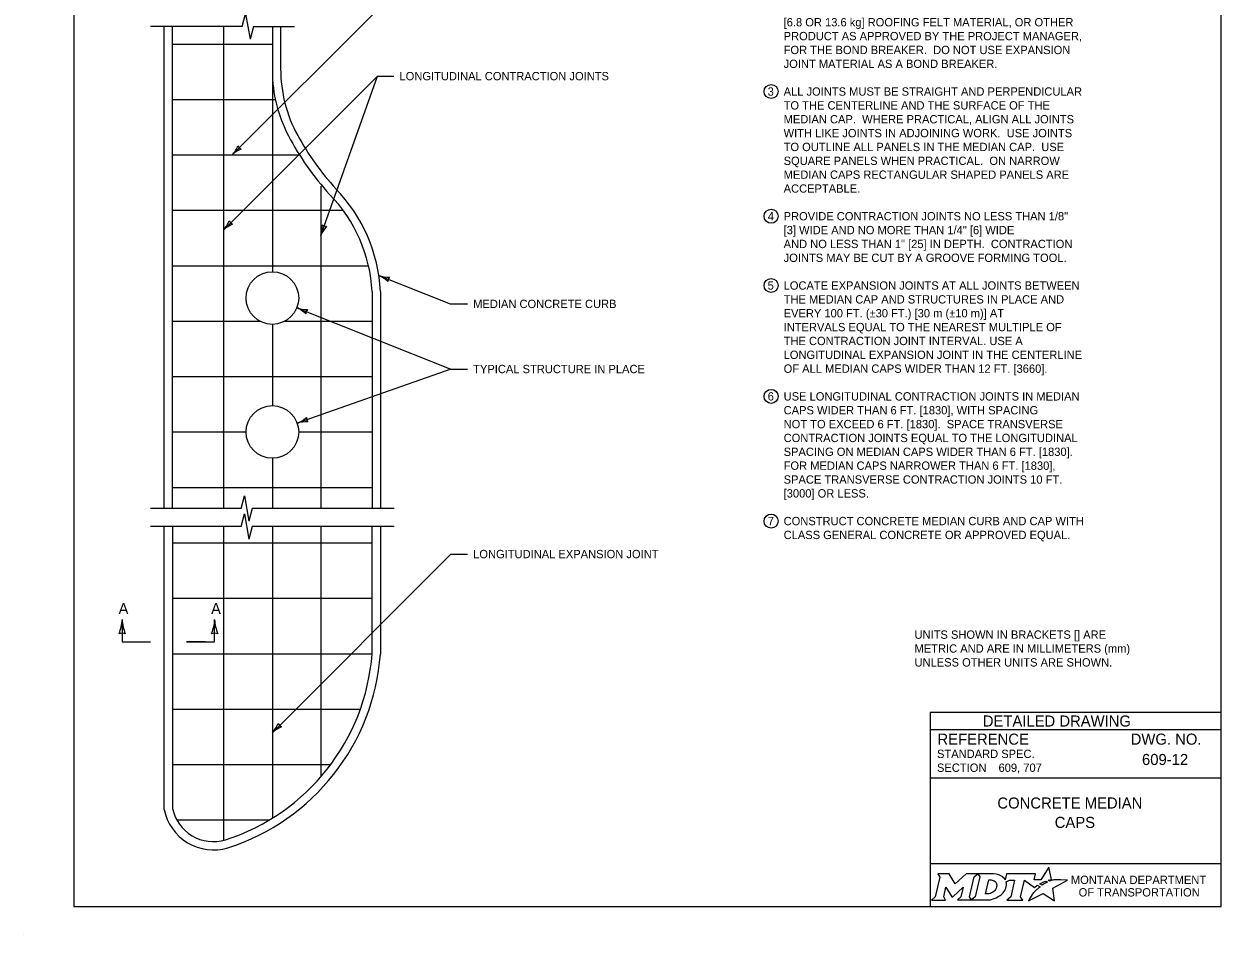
# Model space of a CAD drawing. Extents: x 49991.4 to 50021, y 49987.6 to 50011.4.
# Drawn here: x 49999.98 to 50008.61, y 49999.86 to 50006.43 of the extents above; entities that cross this region are included whole.
import ezdxf

# ---------------------------------------------------------------- set-up
doc = ezdxf.new("R2010")
doc.units = 0
for name, color, linetype in [('Level 1', 7, 'Continuous'), ('Level 2', 7, 'Continuous'), ('Level 3', 7, 'Continuous'), ('Level 6', 7, 'Continuous')]:
    doc.layers.add(name, color=color, linetype=linetype)

msp = doc.modelspace()

# ---------------------------------------------------------------- linework, layer by layer
at = {"layer": 'Level 1'}
for p, q in [((50000.989, 50002.9346), (50000.989, 50006.4113)), ((50001.049, 50002.9346), (50001.049, 50006.4113)), ((50001.4159, 50006.4113), (50001.4159, 50002.9346)), ((50001.769, 50006.4113), (50001.769, 50006.0906)), ((50001.829, 50006.4113), (50001.829, 50006.1057)), ((50001.049, 50006.2857), (50001.769, 50006.2857)), ((50001.769, 50006.0906), (50001.769, 50004.6426)), ((50001.049, 50005.8857), (50001.7902, 50005.8857)), ((50001.049, 50005.4857), (50001.9646, 50005.4857)), ((50002.119, 50005.2604), (50002.119, 50002.9346)), ((50001.049, 50005.0857), (50002.2794, 50005.0857)), ((50001.049, 50004.6857), (50002.4628, 50004.6857)), ((50002.489, 50004.4989), (50002.489, 50002.9346)), ((50002.549, 50004.5005), (50002.549, 50002.9346)), ((50001.049, 50004.2857), (50001.6782, 50004.2857)), ((50001.769, 50004.2626), (50001.769, 50003.6757)), ((50001.8598, 50004.2857), (50002.489, 50004.2857)), ((50001.049, 50003.8857), (50002.489, 50003.8857)), ((50001.049, 50003.4857), (50001.579, 50003.4857)), ((50001.959, 50003.4857), (50002.489, 50003.4857)), ((50001.769, 50003.2957), (50001.769, 50002.9346)), ((50001.049, 50003.0857), (50002.489, 50003.0857)), ((50000.989, 50000.7623), (50000.989, 50002.8048)), ((50001.049, 50002.8048), (50001.049, 50000.7683)), ((50001.4159, 50002.8048), (50001.4159, 50000.5374)), ((50001.769, 50002.8048), (50001.769, 50000.6987)), ((50002.119, 50002.8048), (50002.119, 50000.9971)), ((50002.489, 50001.8857), (50002.489, 50002.8048)), ((50002.549, 50002.8048), (50002.549, 50001.8834)), ((50001.049, 50002.6857), (50002.489, 50002.6857)), ((50001.049, 50002.2857), (50002.489, 50002.2857)), ((50001.049, 50001.8857), (50002.489, 50001.8857)), ((50001.049, 50001.4857), (50002.4042, 50001.4857)), ((50001.049, 50001.0857), (50002.1902, 50001.0857)), ((50001.0798, 50000.6857), (50001.7477, 50000.6857)), ((49999.9766, 49999.8624), (49999.9766, 49999.8624))]:
    msp.add_line(p, q, dxfattribs=at)
msp.add_lwpolyline([(50008.6146, 50011.2628), (50000.3356, 50011.2628), (50000.3356, 50000.0624), (50008.6146, 50000.0624)], close=True, dxfattribs=at)
for centre in [(50001.769, 50004.4526), (50001.769, 50003.4857)]:
    msp.add_circle(centre, 0.19, dxfattribs=at)
for centre, radius, start, end in [((50002.769, 50006.0906), 1, 180, 207.84978), ((50002.829, 50006.1057), 1, 180, 208.70363), ((50003.6924, 50006.5785), 2.0444, 207.84978, 222.39165), ((50003.6924, 50006.5785), 1.9844, 208.70363, 222.39165), ((50001.4021, 50004.4415), 1.1484, 2.9454, 44.18946), ((50001.4021, 50004.4415), 1.0884, 3.02551, 44.18946), ((50001.855, 50004.1793), 0.2223, 45.76443, 65.94794), ((50002.0209, 50004.6028), 0.233, 251.13573, 270.38558), ((50002.0647, 50004.3349), 0.0548, 140.44724, 176.1696), ((50001.8601, 50003.7645), 0.233, 292.23449, 311.48434), ((50002.0692, 50003.5914), 0.0548, 181.546, 217.26836), ((50002.0134, 50003.3362), 0.2223, 86.86319, 107.0467), ((50000.961, 50002.0007), 1.5323, 287.82443, 355.6959), ((50000.961, 50002.0007), 1.5923, 287.80103, 355.77781), ((50001.3442, 50000.8312), 0.3618, 190.97588, 286.64684), ((50001.3442, 50000.8312), 0.3018, 192.02127, 286.53619)]:
    msp.add_arc(centre, radius, start, end, dxfattribs=at)
at = {"layer": 'Level 2'}
for p, q in [((50008.6146, 50001.4624), (50006.5146, 50001.4624)), ((50006.5146, 50001.4624), (50006.5146, 50000.0624)), ((50008.6146, 50001.3374), (50006.5146, 50001.3374)), ((50008.2507, 50001.1223), (50008.2507, 50001.1223)), ((50008.6146, 50000.9874), (50006.5146, 50000.9874)), ((50007.0089, 50001.0629), (50007.0089, 50001.0629)), ((50007.5646, 50000.7383), (50007.5646, 50000.7383)), ((50008.6146, 50000.3693), (50006.5146, 50000.3693))]:
    msp.add_line(p, q, dxfattribs=at)
for points in [[(50006.5701, 50000.2974), (50006.5842, 50000.274), (50006.5507, 50000.1307), (50006.525, 50000.1082), (50006.6266, 50000.1082), (50006.6131, 50000.131), (50006.6293, 50000.2011), (50006.673, 50000.1321), (50006.6783, 50000.1321), (50006.7534, 50000.2016), (50006.737, 50000.1305), (50006.7123, 50000.1085), (50006.8139, 50000.1085), (50006.8001, 50000.1318), (50006.8333, 50000.2742)], [(50006.8333, 50000.2742), (50006.8586, 50000.2974), (50006.7762, 50000.2974), (50006.6966, 50000.2244), (50006.6521, 50000.2971), (50006.5701, 50000.2974)], [(50006.9722, 50000.2974), (50006.8586, 50000.2974), (50006.8733, 50000.2745), (50006.8394, 50000.1307), (50006.8139, 50000.1085), (50006.9245, 50000.1085)], [(50007.3771, 50000.2447), (50007.3668, 50000.2503), (50007.3784, 50000.2531), (50007.39, 50000.2551), (50007.3726, 50000.3452), (50007.3131, 50000.2539), (50007.2658, 50000.2532), (50007.2761, 50000.2973), (50007.0669, 50000.2974), (50007.0568, 50000.2549), (50007.051, 50000.2632)], [(50006.9962, 50000.2107), (50006.995, 50000.2026), (50006.9918, 50000.1933), (50006.9876, 50000.1851), (50006.982, 50000.1776), (50006.9755, 50000.1707), (50006.9676, 50000.1644), (50006.9593, 50000.1597), (50006.9502, 50000.1558), (50006.9411, 50000.1535), (50006.9319, 50000.1526), (50006.916, 50000.1526), (50006.9396, 50000.2526), (50006.9556, 50000.2526), (50006.9632, 50000.252), (50006.9708, 50000.2501), (50006.9774, 50000.2471), (50006.9835, 50000.2429), (50006.9883, 50000.2379), (50006.992, 50000.2319), (50006.9947, 50000.2257), (50006.9963, 50000.2183), (50006.9963, 50000.2153), (50006.9962, 50000.2107)], [(50007.0636, 50000.2383), (50007.0882, 50000.2514), (50007.1251, 50000.2514), (50007.0965, 50000.1309), (50007.069, 50000.1082), (50007.1852, 50000.1082), (50007.1682, 50000.1311), (50007.1964, 50000.2513), (50007.2677, 50000.1996), (50007.2888, 50000.2147), (50007.3085, 50000.2038)], [(50007.2527, 50000.1479), (50007.2374, 50000.1235), (50007.2327, 50000.116), (50007.2269, 50000.1074), (50007.2246, 50000.1031), (50007.3299, 50000.1562), (50007.4138, 50000.1011), (50007.4007, 50000.1938), (50007.5076, 50000.2522), (50007.4583, 50000.253), (50007.4282, 50000.2534), (50007.4074, 50000.2537), (50007.4006, 50000.2522), (50007.3957, 50000.251), (50007.3873, 50000.2487), (50007.3771, 50000.2447)], [(50007.3267, 50000.2171), (50007.3243, 50000.2154), (50007.306, 50000.225), (50007.3163, 50000.2307), (50007.3204, 50000.2329), (50007.329, 50000.2369), (50007.3347, 50000.2395), (50007.3426, 50000.2425), (50007.3499, 50000.2452), (50007.3617, 50000.2378), (50007.3577, 50000.2357), (50007.3531, 50000.2332), (50007.3489, 50000.231), (50007.3439, 50000.2281), (50007.342, 50000.227), (50007.3393, 50000.2254), (50007.3368, 50000.224), (50007.3345, 50000.2224), (50007.3319, 50000.2206), (50007.3292, 50000.2188), (50007.3267, 50000.2171)], [(50006.9702, 50000.1158), (50006.9786, 50000.1184), (50006.9916, 50000.1238), (50007.012, 50000.1348)], [(50007.2666, 50000.164), (50007.2666, 50000.164)]]:
    msp.add_lwpolyline(points, dxfattribs=at)
for centre in [(50005.3678, 50005.9428), (50005.3678, 50005.0428), (50005.3678, 50004.5428), (50005.3678, 50003.7428), (50005.3678, 50002.8428)]:
    msp.add_circle(centre, 0.0505, dxfattribs=at)
for centre, radius, start, end in [((50006.9953, 50000.219), 0.0709, 339.53292, 15.85821), ((50006.9513, 50000.2363), 0.1183, 300.91025, 339.13831)]:
    msp.add_arc(centre, radius, start, end, dxfattribs=at)
for centre, major_axis, ratio, start_param, end_param in [((50006.9701, 50000.25), (0.0834, -0.0037), 0.568097, 0.61298, 1.570796), ((50007.0257, 50000.2573), (0.0361, -0.0295), 0.469099, 1.225588, 1.570796), ((50007.2974, 50000.1941), (-0.0112, -0.0097), 0.021651, 3.157348, 6.283185), ((50006.9248, 50000.2568), (0, 0.1484), 0.987302, 3.139398, 3.456847), ((50007.2597, 50000.1559), (-0.00694, -0.00806), 0.008222, 0, 3.137361), ((50007.2764, 50000.1742), (-0.0098, -0.0102), 0.016458, 3.141593, 6.279097)]:
    msp.add_ellipse(centre, major_axis=major_axis, ratio=ratio, start_param=start_param, end_param=end_param, dxfattribs=at)
at = {"layer": 'Level 3'}
for p, q in [((50001.4789, 50005.4857), (50002.5266, 50006.5333)), ((50001.4159, 50004.9431), (50002.5266, 50006.0538)), ((50002.119, 50004.9044), (50002.5266, 50006.0538)), ((50002.5266, 50006.0538), (50002.6466, 50006.0538)), ((50002.5374, 50004.6148), (50003.0514, 50004.4101)), ((50001.9456, 50004.3823), (50003.0581, 50003.9398)), ((50003.0514, 50004.4101), (50003.1781, 50004.4101)), ((50003.0581, 50003.9398), (50001.9482, 50003.5488)), ((50003.0581, 50003.9398), (50003.1781, 50003.9398)), ((50001.769, 50001.3157), (50003.0581, 50002.6048)), ((50003.0581, 50002.6048), (50003.1781, 50002.6048))]:
    msp.add_line(p, q, dxfattribs=at)
for centre, radius, start, end in [((50001.3062, 50005.6421), 0.233, 317.82731, 337.07716), ((50001.6295, 50005.3221), 0.2223, 112.45601, 132.63952), ((50001.5695, 50005.5763), 0.0548, 207.13882, 242.86118), ((50001.2432, 50005.0995), 0.233, 317.82731, 337.07716), ((50001.5665, 50004.7795), 0.2223, 112.45601, 132.63952), ((50001.5065, 50005.0337), 0.0548, 207.13882, 242.86118), ((50001.8964, 50004.9732), 0.233, 342.82731, 2.07716), ((50002.3246, 50004.8198), 0.2223, 137.45601, 157.63952), ((50002.1629, 50005.0248), 0.0548, 232.13882, 267.86118), ((50002.448, 50004.4113), 0.2223, 46.10006, 66.28356), ((50002.6114, 50004.8358), 0.233, 251.47136, 270.72121), ((50002.6568, 50004.5682), 0.0548, 140.78286, 176.50522), ((50001.5963, 50001.4721), 0.233, 317.82731, 337.07716), ((50001.9196, 50001.1521), 0.2223, 112.45601, 132.63952), ((50001.8597, 50001.4063), 0.0548, 207.13882, 242.86118)]:
    msp.add_arc(centre, radius, start, end, dxfattribs=at)
at = {"layer": 'Level 6'}
for p, q in [((50001.552, 50006.4113), (50001.5762, 50006.5027)), ((50001.5762, 50006.5027), (50001.6086, 50006.3199)), ((50001.552, 50006.4113), (50000.889, 50006.4113)), ((50001.633, 50006.4113), (50001.6086, 50006.3199)), ((50001.633, 50006.4113), (50001.929, 50006.4113)), ((50001.5434, 50002.9346), (50001.5676, 50003.026)), ((50001.5676, 50003.026), (50001.6, 50002.8432)), ((50001.5434, 50002.9346), (50000.889, 50002.9346)), ((50001.5434, 50002.8048), (50001.5676, 50002.8962)), ((50001.5676, 50002.8962), (50001.6, 50002.7134)), ((50001.6244, 50002.9346), (50001.6, 50002.8432)), ((50001.8486, 50002.9346), (50001.6244, 50002.9346)), ((50002.649, 50002.9346), (50001.8486, 50002.9346)), ((50001.5434, 50002.8048), (50000.889, 50002.8048)), ((50001.6244, 50002.8048), (50001.6, 50002.7134)), ((50001.8486, 50002.8048), (50001.6244, 50002.8048)), ((50002.649, 50002.8048), (50001.8486, 50002.8048)), ((50000.6852, 50002.1313), (50000.6852, 50001.972)), ((50001.3528, 50001.972), (50001.3528, 50002.1313)), ((50000.6852, 50001.972), (50000.889, 50001.972)), ((50001.287, 50001.972), (50001.149, 50001.972)), ((50001.149, 50001.972), (50001.3528, 50001.972))]:
    msp.add_line(p, q, dxfattribs=at)
for centre, radius, start, end in [((50000.389, 50002.1435), 0.2964, 337.45601, 357.63952), ((50000.9955, 50002.1466), 0.3107, 182.82731, 202.07716), ((50001.0567, 50002.1435), 0.2964, 337.45601, 357.63952), ((50001.6631, 50002.1466), 0.3107, 182.82731, 202.07716), ((50000.6852, 50001.9603), 0.073, 72.13882, 107.86118), ((50001.3528, 50001.9603), 0.073, 72.13882, 107.86118)]:
    msp.add_arc(centre, radius, start, end, dxfattribs=at)

# ---------------------------------------------------------------- texts
at = {"layer": 'Level 2'}
for s, height, p in [('[6.8 OR 13.6 kg] ROOFING FELT MATERIAL, OR OTHER', 0.06, (50005.4583, 50006.4128)), ('PRODUCT AS APPROVED BY THE PROJECT MANAGER, ', 0.06, (50005.4583, 50006.3128)), ('FOR THE BOND BREAKER.  DO NOT USE EXPANSION ', 0.06, (50005.4583, 50006.2128)), ('JOINT MATERIAL AS A BOND BREAKER.', 0.06, (50005.4583, 50006.1128)), ('LONGITUDINAL CONTRACTION JOINTS', 0.06, (50002.6866, 50006.0238)), ('3', 0.06, (50005.3426, 50005.9128)), ('ALL JOINTS MUST BE STRAIGHT AND PERPENDICULAR', 0.06, (50005.4583, 50005.9128)), ('TO THE CENTERLINE AND THE SURFACE OF THE', 0.06, (50005.4583, 50005.8128)), ('MEDIAN CAP.  WHERE PRACTICAL, ALIGN ALL JOINTS', 0.06, (50005.4583, 50005.7128)), ('WITH LIKE JOINTS IN ADJOINING WORK.  USE JOINTS', 0.06, (50005.4583, 50005.6128)), ('TO OUTLINE ALL PANELS IN THE MEDIAN CAP.  USE', 0.06, (50005.4583, 50005.5128)), ('SQUARE PANELS WHEN PRACTICAL.  ON NARROW', 0.06, (50005.4583, 50005.4128)), ('MEDIAN CAPS RECTANGULAR SHAPED PANELS ARE', 0.06, (50005.4583, 50005.3128)), ('ACCEPTABLE.', 0.06, (50005.4583, 50005.2128)), ('4', 0.06, (50005.3438, 50005.0128)), ('PROVIDE CONTRACTION JOINTS NO LESS THAN 1/8" ', 0.06, (50005.4583, 50005.0128)), ('[3] WIDE AND NO MORE THAN 1/4" [6] WIDE ', 0.06, (50005.4583, 50004.9128)), ('AND NO LESS THAN 1" [25] IN DEPTH.  CONTRACTION ', 0.06, (50005.4583, 50004.8128)), ('JOINTS MAY BE CUT BY A GROOVE FORMING TOOL.', 0.06, (50005.4583, 50004.7128)), ('5', 0.06, (50005.3429, 50004.5128)), ('LOCATE EXPANSION JOINTS AT ALL JOINTS BETWEEN', 0.06, (50005.4583, 50004.5128)), ('MEDIAN CONCRETE CURB', 0.06, (50003.2181, 50004.3801)), ('THE MEDIAN CAP AND STRUCTURES IN PLACE AND', 0.06, (50005.4583, 50004.4128)), ('EVERY 100 FT. (±30 FT.) [30 m (±10 m)] AT ', 0.06, (50005.4583, 50004.3128)), ('INTERVALS EQUAL TO THE NEAREST MULTIPLE OF', 0.06, (50005.4583, 50004.2128)), ('THE CONTRACTION JOINT INTERVAL. USE A ', 0.06, (50005.4583, 50004.1128)), ('LONGITUDINAL EXPANSION JOINT IN THE CENTERLINE ', 0.06, (50005.4583, 50004.0128)), ('TYPICAL STRUCTURE IN PLACE', 0.06, (50003.2181, 50003.9101)), ('OF ALL MEDIAN CAPS WIDER THAN 12 FT. [3660]. ', 0.06, (50005.4583, 50003.9128)), ('6', 0.06, (50005.3432, 50003.7128)), ('USE LONGITUDINAL CONTRACTION JOINTS IN MEDIAN', 0.06, (50005.4583, 50003.7128)), ('CAPS WIDER THAN 6 FT. [1830], WITH SPACING ', 0.06, (50005.4583, 50003.6128)), ('NOT TO EXCEED 6 FT. [1830].  SPACE TRANSVERSE', 0.06, (50005.4583, 50003.5128)), ('CONTRACTION JOINTS EQUAL TO THE LONGITUDINAL', 0.06, (50005.4583, 50003.4128)), ('SPACING ON MEDIAN CAPS WIDER THAN 6 FT. [1830].', 0.06, (50005.4583, 50003.3128)), ('FOR MEDIAN CAPS NARROWER THAN 6 FT. [1830],', 0.06, (50005.4583, 50003.2128)), ('SPACE TRANSVERSE CONTRACTION JOINTS 10 FT. ', 0.06, (50005.4583, 50003.1128)), ('[3000] OR LESS.', 0.06, (50005.4583, 50003.0128)), ('7', 0.06, (50005.344, 50002.8128)), ('CONSTRUCT CONCRETE MEDIAN CURB AND CAP WITH', 0.06, (50005.4583, 50002.8128)), ('CLASS GENERAL CONCRETE OR APPROVED EQUAL.', 0.06, (50005.4583, 50002.7128)), ('LONGITUDINAL EXPANSION JOINT', 0.06, (50003.2181, 50002.5748)), ('A', 0.08, (50000.6591, 50002.1713)), ('A', 0.08, (50001.3267, 50002.1713)), ('UNITS SHOWN IN BRACKETS [] ARE ', 0.06, (50006.4028, 50001.9932)), ('METRIC AND ARE IN MILLIMETERS (mm) ', 0.06, (50006.4028, 50001.8932)), ('UNLESS OTHER UNITS ARE SHOWN.', 0.06, (50006.4028, 50001.7932)), ('DETAILED DRAWING', 0.0799, (50006.8956, 50001.3599)), ('REFERENCE', 0.08, (50006.5682, 50001.229)), ('DWG. NO.', 0.08, (50007.9624, 50001.229)), ('STANDARD SPEC.', 0.06, (50006.5649, 50001.133)), ('609-12', 0.08, (50008.0441, 50001.0823)), ('SECTION', 0.06, (50006.5649, 50001.033)), ('609, 707', 0.06, (50007.0089, 50001.0329)), ('CONCRETE MEDIAN', 0.08, (50007.0007, 50000.7683)), ('CAPS', 0.08, (50007.4142, 50000.6283)), ('MONTANA DEPARTMENT', 0.06, (50007.5308, 50000.2236)), ('OF TRANSPORTATION', 0.06, (50007.587, 50000.1336))]:
    msp.add_text(s, height=height, dxfattribs=at).set_placement(p)

doc.saveas('drawing.dxf')
